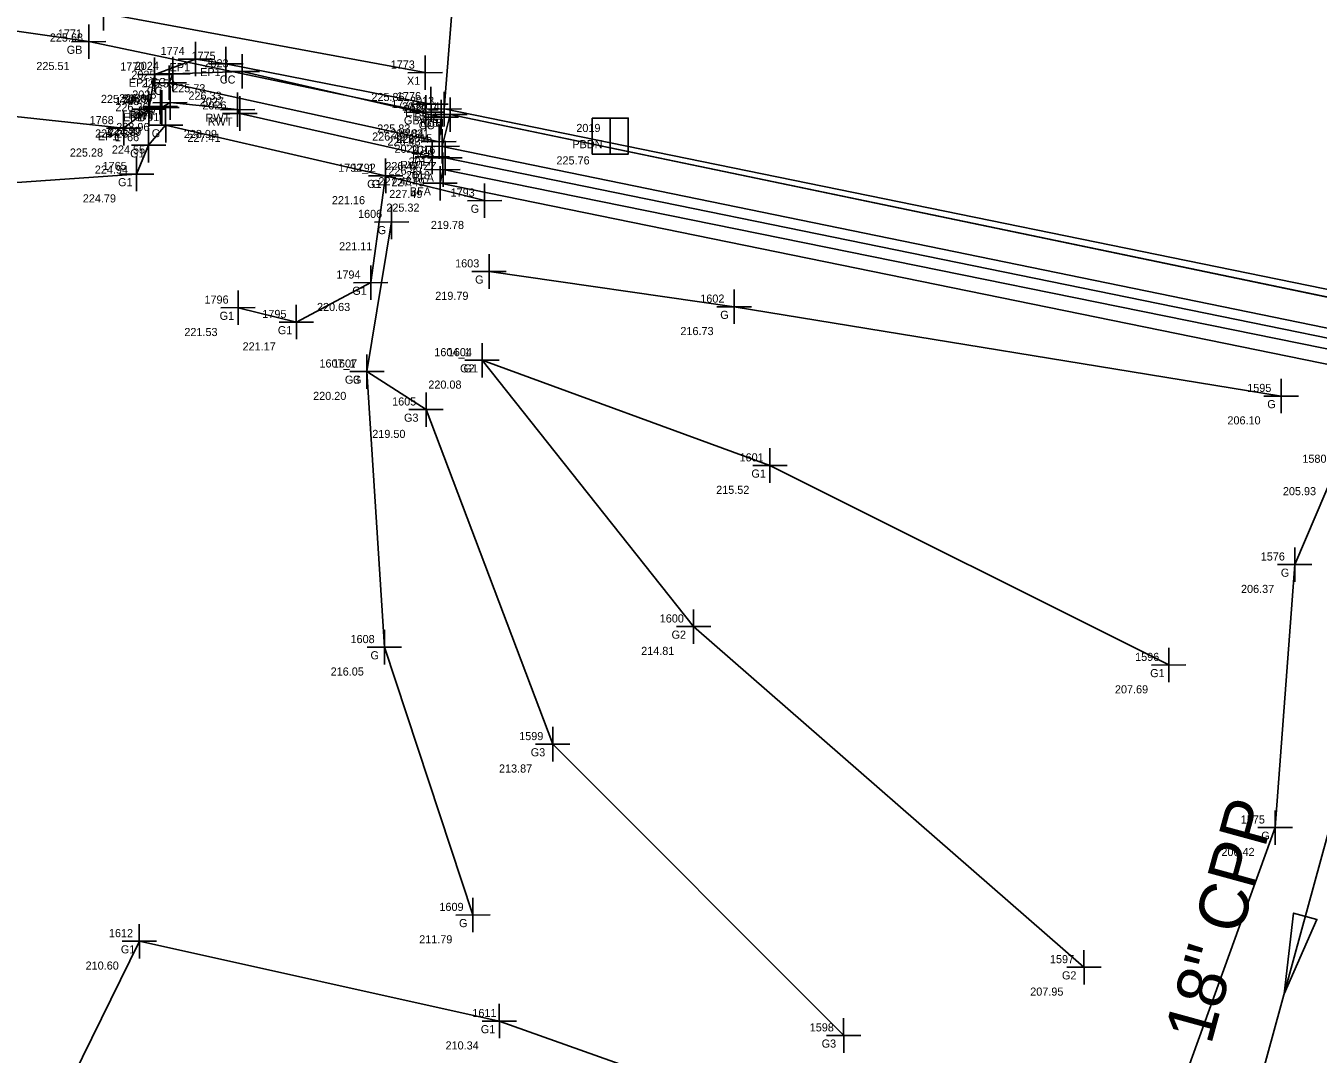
# Model space of a CAD drawing. Extents: x 1158983 to 1160032, y 610902 to 611573.
# Drawn here: x 1159316.41 to 1159364.21, y 611230.37 to 611268.4 of the extents above; entities that cross this region are included whole.
import ezdxf

# ---------------------------------------------------------------- set-up
doc = ezdxf.new("R2010")
doc.units = 0
for name, color, linetype in [('Default', 7, 'Continuous'), ('S_Bridge_Curb', 7, 'Continuous'), ('S_Bridge_Deck', 7, 'Continuous'), ('S_Bridge_Downspout', 7, 'Continuous'), ('S_Bridge_Fascia', 7, 'Continuous'), ('S_Curb_Type_2', 7, 'Continuous'), ('S_Drainage_Culvert_FlowArrow', 7, 'Continuous'), ('S_Drainage_Culvert_Top', 7, 'Continuous'), ('S_Field_Code', 7, 'Continuous'), ('S_Ground_Elevation', 7, 'Continuous'), ('S_Guardrail_Beam', 7, 'Continuous'), ('S_Misc_MiscFeature', 7, 'Continuous'), ('S_Point_Elevation', 7, 'Continuous'), ('S_Point_Name', 7, 'Continuous'), ('S_RetWall_Top', 7, 'Continuous'), ('S_Roadway_Edge_Pavement', 7, 'Continuous'), ('S_Roadway_Edge_TW', 7, 'Continuous'), ('S_Survey_Shot', 7, 'Continuous'), ('S_Text', 7, 'Continuous')]:
    doc.layers.add(name, color=color, linetype=linetype)

msp = doc.modelspace()

# ---------------------------------------------------------------- linework, layer by layer
at = {"layer": 'Default'}
msp.add_line((1159338.026, 611264.327), (1159338.026, 611264.327), dxfattribs=at)
at = {"layer": 'S_Bridge_Curb'}
msp.add_lwpolyline([(1159374.407, 611255.197), (1159374.607, 611256.276), (1159332.105, 611265.121), (1159331.814, 611263.947)], close=True, dxfattribs=at)
at = {"layer": 'S_Bridge_Deck'}
msp.add_lwpolyline([(1159333.801, 611289.348), (1159375.965, 611280.699), (1159433.546, 611269.247), (1159503.551, 611254.972), (1159573.652, 611240.691), (1159630.945, 611229.008), (1159674.004, 611220.503), (1159672.341, 611196.28), (1159630.068, 611204.797), (1159572.75, 611216.514), (1159502.493, 611230.859), (1159432.439, 611245.062), (1159375.072, 611256.503), (1159331.888, 611265.329)], close=True, dxfattribs=at)
at = {"layer": 'S_Bridge_Downspout'}
msp.add_line((1159338.026, 611264.993), (1159338.026, 611263.66), dxfattribs=at)
msp.add_lwpolyline([(1159337.36, 611264.993), (1159338.693, 611264.993), (1159338.693, 611263.66), (1159337.36, 611263.66)], close=True, dxfattribs=at)
at = {"layer": 'S_Bridge_Fascia'}
msp.add_lwpolyline([(1159374.365, 611253.879), (1159374.366, 611254.457), (1159331.842, 611263.085), (1159331.733, 611262.58)], close=True, dxfattribs=at)
at = {"layer": 'S_Curb_Type_2'}
msp.add_lwpolyline([(1159331.696, 611264.119), (1159331.775, 611265.027), (1159324.416, 611266.719), (1159321.853, 611266.625), (1159321.713, 611266.298)], close=True, dxfattribs=at)
at = {"layer": 'S_Drainage_Culvert_FlowArrow'}
msp.add_line((1159362.947, 611232.604), (1159362.947, 611232.604), dxfattribs=at)
msp.add_lwpolyline([(1159362.947, 611232.604), (1159363.302, 611235.583), (1159364.16, 611235.348)], close=True, dxfattribs=at)
at = {"layer": 'S_Drainage_Culvert_Top'}
msp.add_lwpolyline([(1159357.648, 611213.251), (1159368.247, 611251.957)], dxfattribs=at)
at = {"layer": 'S_Ground_Elevation'}
for points in [[(1159002.468, 611332.247), (1159049.059, 611320.284), (1159092.698, 611304.371), (1159123.586, 611293.695), (1159160.419, 611290.876), (1159212.254, 611279.83), (1159269.173, 611267.751), (1159315.368, 611262.554), (1159320.509, 611262.922), (1159320.954, 611263.987)], [(1159355.399, 611212.784), (1159354.868, 611217.296), (1159362.619, 611238.747), (1159363.344, 611248.476), (1159364.893, 611252.092), (1159367.286, 611253.012), (1159367.04, 611258.265), (1159369.176, 611279.512)], [(1159320.954, 611263.987), (1159321.584, 611264.729)], [(1159321.584, 611264.729), (1159329.72, 611262.856), (1159333.38, 611261.939)], [(1159329.72, 611262.856), (1159329.17, 611258.905), (1159326.417, 611257.447), (1159324.264, 611257.979)], [(1159329.939, 611261.149), (1159329.027, 611255.616), (1159329.675, 611245.421), (1159332.949, 611235.515)], [(1159362.842, 611254.711), (1159342.61, 611258.015), (1159333.544, 611259.319)], [(1159358.681, 611244.762), (1159343.933, 611252.142), (1159333.287, 611256.034)], [(1159355.548, 611233.581), (1159341.109, 611246.184), (1159333.287, 611256.034)], [(1159346.66, 611231.058), (1159335.901, 611241.833), (1159331.214, 611254.21), (1159329.027, 611255.616)], [(1159343.602, 611228.151), (1159333.924, 611231.59), (1159320.612, 611234.544), (1159314.265, 611221.651), (1159310.207, 611192.625), (1159301.313, 611165.491), (1159294.216, 611125.97), (1159281.365, 611085.012)]]:
    msp.add_lwpolyline(points, dxfattribs=at)
at = {"layer": 'S_Guardrail_Beam'}
for points in [[(1159331.21, 611265.209), (1159318.741, 611267.819), (1159270.451, 611274.775), (1159214.189, 611285.337), (1159152.222, 611298.369), (1159139.375, 611300.216), (1159124.684, 611301.028)], [(1159962.355, 611128.723), (1159954.927, 611131.331), (1159940.804, 611136.335), (1159922.846, 611140.981), (1159878.137, 611150.269), (1159824.181, 611161.329), (1159771.192, 611171.967), (1159724.558, 611182.82), (1159696.585, 611190.71), (1159683.564, 611193.82), (1159671.877, 611196.264), (1159629.625, 611204.61), (1159571.633, 611216.492), (1159501.577, 611230.682), (1159431.638, 611244.705), (1159374.182, 611256.374), (1159332.105, 611265.121)]]:
    msp.add_lwpolyline(points, dxfattribs=at)
at = {"layer": 'S_Misc_MiscFeature'}
msp.add_lwpolyline([(1159374.405, 611254.846), (1159331.92, 611263.519)], dxfattribs=at)
at = {"layer": 'S_RetWall_Top'}
msp.add_lwpolyline([(1159331.443, 611263.557), (1159324.325, 611265.162), (1159324.244, 611265.304), (1159321.746, 611265.563), (1159321.444, 611265.385), (1159321.388, 611265.418)], dxfattribs=at)
at = {"layer": 'S_Roadway_Edge_Pavement'}
msp.add_lwpolyline([(1159002.959, 611334.174), (1159050.7, 611322.62), (1159054.98, 611321.505), (1159089.669, 611308.424), (1159113.692, 611299.145), (1159158.379, 611294.14), (1159213.256, 611283.037), (1159269.989, 611270.734), (1159313.952, 611265.271), (1159320.03, 611264.618), (1159320.963, 611265.323), (1159321.178, 611266.601), (1159322.686, 611267.176), (1159323.814, 611266.995), (1159331.397, 611265.506)], dxfattribs=at)
at = {"layer": 'S_Roadway_Edge_TW'}
msp.add_lwpolyline([(1159003.943, 611338.028), (1159051.315, 611326.497), (1159095.593, 611316.459), (1159127.862, 611309.062), (1159159.052, 611302.124), (1159217.512, 611289.831), (1159271.817, 611278.631), (1159319.29, 611268.871), (1159331.181, 611266.673)], dxfattribs=at)
at = {"layer": 'S_Survey_Shot'}
for p, q in [((1159319.291, 611268.235), (1159319.289, 611269.507)), ((1159318.742, 611267.183), (1159318.739, 611268.455)), ((1159318.105, 611267.818), (1159319.377, 611267.82)), ((1159318.741, 611267.819), (1159318.741, 611267.819)), ((1159322.687, 611266.54), (1159322.684, 611267.812)), ((1159321.179, 611265.965), (1159321.176, 611267.238)), ((1159321.854, 611265.989), (1159321.852, 611267.261)), ((1159323.815, 611266.359), (1159323.813, 611267.631)), ((1159324.418, 611266.083), (1159324.415, 611267.356)), ((1159331.183, 611266.037), (1159331.18, 611267.309)), ((1159321.715, 611265.662), (1159321.712, 611266.934)), ((1159322.05, 611267.175), (1159323.322, 611267.177)), ((1159322.686, 611267.176), (1159322.686, 611267.176)), ((1159323.178, 611266.994), (1159324.45, 611266.996)), ((1159323.78, 611266.718), (1159325.052, 611266.721)), ((1159323.814, 611266.995), (1159323.814, 611266.995)), ((1159324.416, 611266.719), (1159324.416, 611266.719)), ((1159320.541, 611266.6), (1159321.814, 611266.603)), ((1159321.077, 611266.296), (1159322.35, 611266.299)), ((1159321.178, 611266.601), (1159321.178, 611266.601)), ((1159321.217, 611266.624), (1159322.489, 611266.627)), ((1159321.713, 611266.298), (1159321.713, 611266.298)), ((1159321.853, 611266.625), (1159321.853, 611266.625)), ((1159330.545, 611266.671), (1159331.818, 611266.674)), ((1159331.181, 611266.673), (1159331.181, 611266.673)), ((1159320.965, 611264.687), (1159320.962, 611265.959)), ((1159321.39, 611264.782), (1159321.387, 611266.054)), ((1159321.446, 611264.749), (1159321.443, 611266.022)), ((1159321.748, 611264.927), (1159321.745, 611266.199)), ((1159324.245, 611264.668), (1159324.242, 611265.94)), ((1159324.327, 611264.526), (1159324.324, 611265.798)), ((1159331.212, 611264.573), (1159331.209, 611265.845)), ((1159331.398, 611264.87), (1159331.396, 611266.143)), ((1159331.889, 611264.692), (1159331.886, 611265.965)), ((1159332.106, 611264.485), (1159332.103, 611265.757)), ((1159332.106, 611264.485), (1159332.103, 611265.757)), ((1159320.327, 611265.322), (1159321.6, 611265.324)), ((1159320.752, 611265.416), (1159322.025, 611265.419)), ((1159320.808, 611265.384), (1159322.08, 611265.387)), ((1159320.963, 611265.323), (1159320.963, 611265.323)), ((1159321.11, 611265.562), (1159322.382, 611265.565)), ((1159321.388, 611265.418), (1159321.388, 611265.418)), ((1159321.444, 611265.385), (1159321.444, 611265.385)), ((1159321.586, 611264.092), (1159321.583, 611265.365)), ((1159321.746, 611265.563), (1159321.746, 611265.563)), ((1159323.607, 611265.303), (1159324.88, 611265.306)), ((1159324.244, 611265.304), (1159324.244, 611265.304)), ((1159330.761, 611265.505), (1159332.033, 611265.508)), ((1159331.251, 611265.327), (1159332.524, 611265.33)), ((1159331.397, 611265.506), (1159331.397, 611265.506)), ((1159331.776, 611264.391), (1159331.773, 611265.664)), ((1159331.888, 611265.329), (1159331.888, 611265.329)), ((1159320.032, 611263.982), (1159320.029, 611265.254)), ((1159323.689, 611265.161), (1159324.962, 611265.163)), ((1159324.325, 611265.162), (1159324.325, 611265.162)), ((1159330.574, 611265.207), (1159331.847, 611265.21)), ((1159331.139, 611265.026), (1159332.411, 611265.029)), ((1159331.21, 611265.209), (1159331.21, 611265.209)), ((1159331.469, 611265.12), (1159332.741, 611265.123)), ((1159331.469, 611265.12), (1159332.741, 611265.123)), ((1159331.775, 611265.027), (1159331.775, 611265.027)), ((1159332.105, 611265.121), (1159332.105, 611265.121)), ((1159332.105, 611265.121), (1159332.105, 611265.121)), ((1159319.394, 611264.617), (1159320.666, 611264.619)), ((1159320.03, 611264.618), (1159320.03, 611264.618)), ((1159320.948, 611264.727), (1159322.221, 611264.73)), ((1159320.955, 611263.351), (1159320.952, 611264.623)), ((1159321.584, 611264.729), (1159321.584, 611264.729)), ((1159331.697, 611263.483), (1159331.694, 611264.756)), ((1159331.816, 611263.311), (1159331.813, 611264.583)), ((1159320.317, 611263.986), (1159321.59, 611263.989)), ((1159320.954, 611263.987), (1159320.954, 611263.987)), ((1159331.06, 611264.118), (1159332.332, 611264.121)), ((1159331.178, 611263.946), (1159332.451, 611263.949)), ((1159331.444, 611262.921), (1159331.441, 611264.193)), ((1159331.696, 611264.119), (1159331.696, 611264.119)), ((1159331.814, 611263.947), (1159331.814, 611263.947)), ((1159331.921, 611262.883), (1159331.919, 611264.155)), ((1159320.511, 611262.285), (1159320.508, 611263.558)), ((1159329.721, 611262.22), (1159329.719, 611263.492)), ((1159329.721, 611262.22), (1159329.719, 611263.492)), ((1159330.806, 611263.556), (1159332.079, 611263.559)), ((1159331.284, 611263.518), (1159332.556, 611263.52)), ((1159331.443, 611263.557), (1159331.443, 611263.557)), ((1159331.843, 611262.449), (1159331.84, 611263.721)), ((1159331.92, 611263.519), (1159331.92, 611263.519)), ((1159319.873, 611262.92), (1159321.145, 611262.923)), ((1159320.509, 611262.922), (1159320.509, 611262.922)), ((1159331.205, 611263.084), (1159332.478, 611263.086)), ((1159331.734, 611261.944), (1159331.731, 611263.216)), ((1159331.842, 611263.085), (1159331.842, 611263.085)), ((1159329.084, 611262.855), (1159330.356, 611262.857)), ((1159329.084, 611262.855), (1159330.356, 611262.857)), ((1159329.72, 611262.856), (1159329.72, 611262.856)), ((1159329.72, 611262.856), (1159329.72, 611262.856)), ((1159331.096, 611262.579), (1159332.369, 611262.582)), ((1159331.733, 611262.58), (1159331.733, 611262.58)), ((1159333.381, 611261.302), (1159333.379, 611262.575)), ((1159332.744, 611261.937), (1159334.016, 611261.94)), ((1159333.38, 611261.939), (1159333.38, 611261.939)), ((1159329.94, 611260.513), (1159329.937, 611261.785)), ((1159329.302, 611261.148), (1159330.575, 611261.15)), ((1159329.939, 611261.149), (1159329.939, 611261.149)), ((1159329.171, 611258.269), (1159329.168, 611259.541)), ((1159333.546, 611258.682), (1159333.543, 611259.955)), ((1159332.908, 611259.317), (1159334.18, 611259.32)), ((1159333.544, 611259.319), (1159333.544, 611259.319)), ((1159324.265, 611257.343), (1159324.262, 611258.616)), ((1159328.533, 611258.903), (1159329.806, 611258.906)), ((1159329.17, 611258.905), (1159329.17, 611258.905)), ((1159342.612, 611257.378), (1159342.609, 611258.651)), ((1159323.627, 611257.978), (1159324.9, 611257.981)), ((1159324.264, 611257.979), (1159324.264, 611257.979)), ((1159326.419, 611256.811), (1159326.416, 611258.083)), ((1159341.974, 611258.013), (1159343.246, 611258.016)), ((1159342.61, 611258.015), (1159342.61, 611258.015)), ((1159325.781, 611257.446), (1159327.054, 611257.448)), ((1159326.417, 611257.447), (1159326.417, 611257.447)), ((1159333.288, 611255.398), (1159333.285, 611256.67)), ((1159333.288, 611255.398), (1159333.285, 611256.67)), ((1159329.029, 611254.979), (1159329.026, 611256.252)), ((1159329.029, 611254.979), (1159329.026, 611256.252)), ((1159332.65, 611256.033), (1159333.923, 611256.036)), ((1159332.65, 611256.033), (1159333.923, 611256.036)), ((1159333.287, 611256.034), (1159333.287, 611256.034)), ((1159333.287, 611256.034), (1159333.287, 611256.034)), ((1159328.391, 611255.614), (1159329.663, 611255.617)), ((1159328.391, 611255.614), (1159329.663, 611255.617)), ((1159329.027, 611255.616), (1159329.027, 611255.616)), ((1159329.027, 611255.616), (1159329.027, 611255.616)), ((1159362.843, 611254.075), (1159362.84, 611255.347)), ((1159331.215, 611253.574), (1159331.213, 611254.846)), ((1159362.205, 611254.709), (1159363.478, 611254.712)), ((1159362.842, 611254.711), (1159362.842, 611254.711)), ((1159330.578, 611254.208), (1159331.85, 611254.211)), ((1159331.214, 611254.21), (1159331.214, 611254.21)), ((1159343.935, 611251.506), (1159343.932, 611252.778)), ((1159343.297, 611252.141), (1159344.569, 611252.143)), ((1159343.933, 611252.142), (1159343.933, 611252.142)), ((1159363.345, 611247.84), (1159363.342, 611249.112)), ((1159362.707, 611248.475), (1159363.98, 611248.477)), ((1159363.344, 611248.476), (1159363.344, 611248.476)), ((1159341.111, 611245.548), (1159341.108, 611246.82)), ((1159340.473, 611246.183), (1159341.746, 611246.185)), ((1159341.109, 611246.184), (1159341.109, 611246.184)), ((1159329.676, 611244.784), (1159329.674, 611246.057)), ((1159329.039, 611245.419), (1159330.311, 611245.422)), ((1159329.675, 611245.421), (1159329.675, 611245.421)), ((1159358.683, 611244.126), (1159358.68, 611245.398)), ((1159358.045, 611244.761), (1159359.318, 611244.763)), ((1159358.681, 611244.762), (1159358.681, 611244.762)), ((1159335.902, 611241.197), (1159335.9, 611242.469)), ((1159335.265, 611241.832), (1159336.537, 611241.834)), ((1159335.901, 611241.833), (1159335.901, 611241.833)), ((1159362.62, 611238.111), (1159362.618, 611239.383)), ((1159361.983, 611238.746), (1159363.255, 611238.748)), ((1159362.619, 611238.747), (1159362.619, 611238.747)), ((1159332.95, 611234.879), (1159332.948, 611236.151)), ((1159320.613, 611233.908), (1159320.61, 611235.181)), ((1159332.313, 611235.514), (1159333.585, 611235.516)), ((1159332.949, 611235.515), (1159332.949, 611235.515)), ((1159319.975, 611234.543), (1159321.248, 611234.546)), ((1159320.612, 611234.544), (1159320.612, 611234.544)), ((1159355.549, 611232.945), (1159355.546, 611234.217)), ((1159354.911, 611233.58), (1159356.184, 611233.583)), ((1159355.548, 611233.581), (1159355.548, 611233.581)), ((1159333.925, 611230.954), (1159333.923, 611232.227)), ((1159333.288, 611231.589), (1159334.56, 611231.592)), ((1159333.924, 611231.59), (1159333.924, 611231.59)), ((1159346.662, 611230.422), (1159346.659, 611231.694)), ((1159346.024, 611231.056), (1159347.296, 611231.059)), ((1159346.66, 611231.058), (1159346.66, 611231.058))]:
    msp.add_line(p, q, dxfattribs=at)

# ---------------------------------------------------------------- texts
at = {"layer": 'S_Field_Code'}
for s, p in [('GB', (1159317.926, 611267.369)), ('EP1', (1159321.729, 611266.726)), ('EP1', (1159322.857, 611266.545)), ('EP1', (1159320.221, 611266.151)), ('CC', (1159321.024, 611266.175)), ('CC', (1159323.587, 611266.269)), ('X1', (1159330.51, 611266.223)), ('CC', (1159320.884, 611265.848)), ('RWT', (1159320.56, 611265.113)), ('EP1', (1159330.441, 611265.056)), ('EP1', (1159320.007, 611264.873)), ('RWT', (1159320.203, 611264.968)), ('RWT', (1159320.258, 611264.935)), ('RWT', (1159323.058, 611264.854)), ('RWT', (1159323.14, 611264.712)), ('GB', (1159330.395, 611264.759)), ('BDK', (1159330.787, 611264.879)), ('CC', (1159330.946, 611264.577)), ('BCB', (1159330.99, 611264.671)), ('GB1', (1159331.12, 611264.671)), ('EP1', (1159319.074, 611264.168)), ('G', (1159321.069, 611264.279)), ('G1', (1159320.269, 611263.537)), ('CC', (1159330.867, 611263.669)), ('PBDN', (1159336.625, 611263.877)), ('RWT', (1159330.257, 611263.107)), ('BCB', (1159330.699, 611263.497)), ('ZZ', (1159331.119, 611263.069)), ('BFA', (1159330.725, 611262.635)), ('G1', (1159319.824, 611262.471)), ('G1', (1159329.035, 611262.406)), ('G', (1159329.205, 611262.406)), ('BFA', (1159330.615, 611262.13)), ('G', (1159332.865, 611261.489)), ('G', (1159329.424, 611260.699)), ('G', (1159333.029, 611258.869)), ('G1', (1159328.485, 611258.455)), ('G1', (1159323.579, 611257.529)), ('G', (1159342.095, 611257.565)), ('G1', (1159325.732, 611256.997)), ('G2', (1159332.472, 611255.584)), ('G1', (1159332.602, 611255.584)), ('G3', (1159328.212, 611255.166)), ('G', (1159328.512, 611255.166)), ('G', (1159362.327, 611254.261)), ('G3', (1159330.399, 611253.76)), ('G1', (1159343.248, 611251.692)), ('G', (1159362.829, 611248.026)), ('G2', (1159340.294, 611245.734)), ('G', (1159329.16, 611244.971)), ('G1', (1159357.996, 611244.312)), ('G3', (1159335.086, 611241.383)), ('G', (1159362.104, 611238.297)), ('G', (1159332.434, 611235.065)), ('G1', (1159319.927, 611234.094)), ('G2', (1159354.733, 611233.131)), ('G1', (1159333.239, 611231.14)), ('G3', (1159345.845, 611230.608))]:
    msp.add_text(s, height=0.3, dxfattribs=at).set_placement(p)
at = {"layer": 'S_Point_Elevation'}
for s, p in [('225.68', (1159317.301, 611267.821)), ('225.51', (1159316.801, 611266.769)), ('225.59', (1159320.697, 611266.126)), ('225.73', (1159321.825, 611265.945)), ('225.53', (1159319.189, 611265.551)), ('226.30', (1159319.864, 611265.575)), ('226.33', (1159322.427, 611265.669)), ('225.86', (1159329.192, 611265.623)), ('226.36', (1159319.724, 611265.248)), ('228.96', (1159319.757, 611264.513)), ('225.28', (1159318.974, 611264.273)), ('227.40', (1159319.399, 611264.368)), ('227.39', (1159319.455, 611264.335)), ('228.99', (1159322.255, 611264.254)), ('227.41', (1159322.386, 611264.112)), ('226.45', (1159329.221, 611264.159)), ('225.83', (1159329.408, 611264.456)), ('225.84', (1159329.899, 611264.279)), ('226.44', (1159330.116, 611264.071)), ('226.44', (1159330.116, 611264.071)), ('225.28', (1159318.041, 611263.568)), ('224.55', (1159319.595, 611263.679)), ('226.43', (1159329.786, 611263.977)), ('226.47', (1159329.707, 611263.069)), ('225.76', (1159336.037, 611263.277)), ('224.94', (1159318.965, 611262.937)), ('226.49', (1159329.825, 611262.897)), ('227.48', (1159329.454, 611262.507)), ('227.49', (1159329.931, 611262.469)), ('224.79', (1159318.52, 611261.872)), ('221.16', (1159327.731, 611261.806)), ('221.16', (1159327.731, 611261.806)), ('227.49', (1159329.853, 611262.035)), ('225.32', (1159329.744, 611261.53)), ('219.78', (1159331.391, 611260.889)), ('221.11', (1159327.999, 611260.099)), ('220.63', (1159327.181, 611257.855)), ('219.79', (1159331.555, 611258.269)), ('221.53', (1159322.275, 611256.929)), ('216.73', (1159340.621, 611256.965)), ('221.17', (1159324.428, 611256.397)), ('220.08', (1159331.298, 611254.984)), ('220.08', (1159331.298, 611254.984)), ('220.20', (1159327.038, 611254.566)), ('220.20', (1159327.038, 611254.566)), ('206.10', (1159360.853, 611253.661)), ('219.50', (1159329.225, 611253.16)), ('215.52', (1159341.944, 611251.092)), ('205.93', (1159362.904, 611251.042)), ('206.37', (1159361.355, 611247.426)), ('214.81', (1159339.17, 611245.134)), ('216.05', (1159327.686, 611244.371)), ('207.69', (1159356.692, 611243.712)), ('213.87', (1159333.912, 611240.783)), ('206.42', (1159360.63, 611237.697)), ('211.79', (1159330.96, 611234.465)), ('210.60', (1159318.623, 611233.494)), ('207.95', (1159353.559, 611232.531)), ('210.34', (1159331.935, 611230.54))]:
    msp.add_text(s, height=0.3, dxfattribs=at).set_placement(p)
at = {"layer": 'S_Point_Name'}
for s, p in [('1771', (1159317.595, 611267.969)), ('1774', (1159321.396, 611267.326)), ('1775', (1159322.539, 611267.145)), ('1770', (1159319.905, 611266.751)), ('2025', (1159320.315, 611266.448)), ('2024', (1159320.441, 611266.775)), ('2023', (1159323.018, 611266.869)), ('1773', (1159329.906, 611266.823)), ('1769', (1159319.719, 611265.473)), ('2030', (1159319.992, 611265.568)), ('2029', (1159320.06, 611265.535)), ('2028', (1159320.348, 611265.713)), ('2027', (1159322.843, 611265.454)), ('1776', (1159330.136, 611265.656)), ('2013', (1159330.619, 611265.479)), ('2026', (1159322.941, 611265.312)), ('1777', (1159329.933, 611265.359)), ('2014_1', (1159330.324, 611265.271)), ('2022', (1159330.376, 611265.177)), ('2014', (1159330.822, 611265.271)), ('1768', (1159318.771, 611264.768)), ('1791', (1159320.456, 611264.879)), ('1766', (1159319.709, 611264.137)), ('2021', (1159330.427, 611264.269)), ('2015', (1159330.546, 611264.097)), ('2019', (1159336.772, 611264.477)), ('2020', (1159330.047, 611263.707)), ('2016', (1159330.666, 611263.669)), ('1765', (1159319.25, 611263.072)), ('2017', (1159330.571, 611263.235)), ('1792_1', (1159327.963, 611263.006)), ('1792', (1159328.461, 611263.006)), ('2018', (1159330.464, 611262.73)), ('1793', (1159332.121, 611262.089)), ('1606', (1159328.699, 611261.299)), ('1603', (1159332.29, 611259.469)), ('1794', (1159327.897, 611259.055)), ('1796', (1159323.019, 611258.129)), ('1602', (1159341.356, 611258.165)), ('1795', (1159325.158, 611257.597)), ('1604_1', (1159331.52, 611256.184)), ('1604', (1159332.018, 611256.184)), ('1607_1', (1159327.272, 611255.766)), ('1607', (1159327.771, 611255.766)), ('1595', (1159361.585, 611254.861)), ('1605', (1159329.96, 611254.36)), ('1601', (1159342.809, 611252.292)), ('1580', (1159363.624, 611252.242)), ('1576', (1159362.085, 611248.626)), ('1600', (1159339.858, 611246.334)), ('1608', (1159328.421, 611245.571)), ('1596', (1159357.439, 611244.912)), ('1599', (1159334.659, 611241.983)), ('1575', (1159361.346, 611238.897)), ('1609', (1159331.709, 611235.665)), ('1612', (1159319.485, 611234.694)), ('1597', (1159354.289, 611233.731)), ('1611', (1159332.927, 611231.74)), ('1598', (1159345.404, 611231.208))]:
    msp.add_text(s, height=0.3, dxfattribs=at).set_placement(p)
at = {"layer": 'S_Text'}
msp.add_text('18" CPP', height=1.8, rotation=74.6863, dxfattribs=at).set_placement((1159360.243, 611230.678))

doc.saveas('drawing.dxf')
